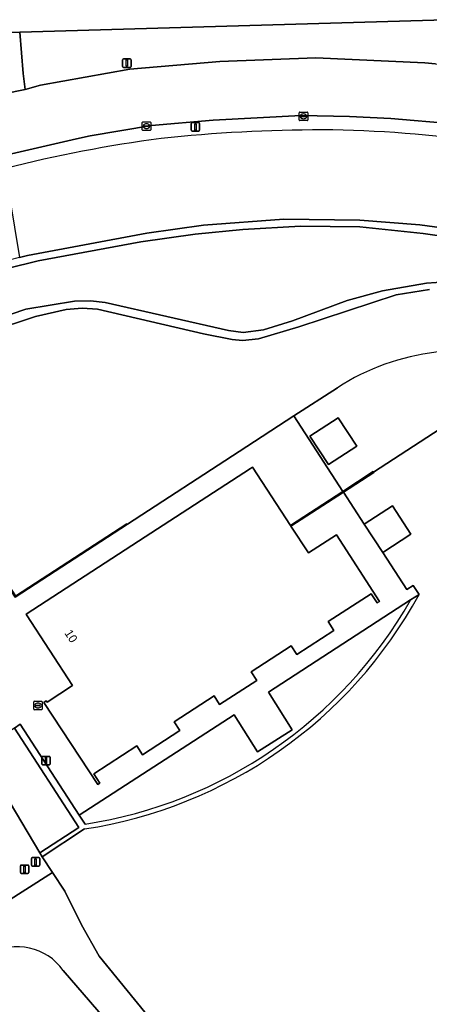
# Model space of a CAD drawing. Extents: x 159451 to 160664, y 388402 to 389723.
# Drawn here: x 160045.5 to 160093.7, y 389263 to 389378.7 of the extents above; entities that cross this region are included whole.
import ezdxf

# ---------------------------------------------------------------- set-up
doc = ezdxf.new("R2010")
doc.units = 0
for name, color, linetype in [('IMGEO_Afsluitpaal', 7, 'Continuous'), ('IMGEO_Erf', 7, 'Continuous'), ('IMGEO_Grasland_overig', 7, 'Continuous'), ('IMGEO_Groenvoorziening', 7, 'Continuous'), ('IMGEO_Haag', 7, 'Continuous'), ('IMGEO_Kolk', 7, 'Continuous'), ('IMGEO_Lichtmast', 7, 'Continuous'), ('IMGEO_Loofbos', 7, 'Continuous'), ('IMGEO_Meer_plas_ven_vijver', 7, 'Continuous'), ('IMGEO_Muur', 7, 'Continuous'), ('IMGEO_Oever', 7, 'Continuous'), ('IMGEO_Open_loods', 7, 'Continuous'), ('IMGEO_Pand', 7, 'Continuous'), ('IMGEO_Pand_nummerreeks', 7, 'Continuous'), ('IMGEO_Parkeervlak_open', 7, 'Continuous'), ('IMGEO_Rijbaan_lokaal_gesloten', 7, 'Continuous'), ('IMGEO_Rijbaan_lokaal_open', 7, 'Continuous'), ('IMGEO_Rioolput', 7, 'Continuous'), ('IMGEO_Verkeersbordpaal', 7, 'Continuous'), ('IMGEO_Voetpad_open', 7, 'Continuous')]:
    doc.layers.add(name, color=color, linetype=linetype)

msp = doc.modelspace()

# ---------------------------------------------------------------- linework, layer by layer
at = {"layer": 'IMGEO_Afsluitpaal'}
for p, q in [((160047.01, 389280.19), (160047.8, 389280.19)), ((160047.8, 389280.19), (160047.01, 389280.19)), ((160045.62, 389278.43), (160045.62, 389279.22)), ((160045.62, 389279.22), (160045.62, 389278.43)), ((160045.72, 389279.32), (160046.51, 389279.32)), ((160046.51, 389279.32), (160045.72, 389279.32)), ((160046.61, 389279.22), (160046.61, 389278.43)), ((160046.61, 389278.43), (160046.61, 389279.22)), ((160046.91, 389279.29), (160046.91, 389280.09)), ((160046.91, 389280.09), (160046.91, 389279.29)), ((160047.8, 389279.19), (160047.01, 389279.19)), ((160047.01, 389279.19), (160047.8, 389279.19)), ((160047.9, 389280.09), (160047.9, 389279.29)), ((160047.9, 389279.29), (160047.9, 389280.09)), ((160046.51, 389278.33), (160045.72, 389278.33)), ((160045.72, 389278.33), (160046.51, 389278.33))]:
    msp.add_line(p, q, dxfattribs=at)
for points in [[(160046.04, 389279.2), (160046.19, 389279.2), (160046.19, 389278.45), (160046.04, 389278.45), (160046.04, 389279.2)], [(160047.33, 389280.06), (160047.48, 389280.06), (160047.48, 389279.31), (160047.33, 389279.31), (160047.33, 389280.06)]]:
    msp.add_lwpolyline(points, dxfattribs=at)
for centre, start, end in [((160047.01, 389280.09), 90, 180), ((160047.01, 389280.09), 90, 180), ((160047.8, 389280.09), 0, 90), ((160047.8, 389280.09), 360, 90), ((160045.72, 389279.22), 90, 180), ((160045.72, 389279.22), 90, 180), ((160046.51, 389279.22), 0, 90), ((160046.51, 389279.22), 360, 90), ((160047.01, 389279.29), 180, 270), ((160047.01, 389279.29), 180, 270), ((160047.8, 389279.29), 270, 0), ((160047.8, 389279.29), 270, 0), ((160045.72, 389278.43), 180, 270), ((160045.72, 389278.43), 180, 270), ((160046.51, 389278.43), 270, 0), ((160046.51, 389278.43), 270, 0)]:
    msp.add_arc(centre, 0.1, start, end, dxfattribs=at)
at = {"layer": 'IMGEO_Erf'}
msp.add_lwpolyline([(160062.76, 389252.92), (160050.65, 389266.93)], dxfattribs=at)
msp.add_arc((160045.28, 389263.1), 6.6, 35.5165, 119.9336, dxfattribs=at)
at = {"layer": 'IMGEO_Grasland_overig'}
msp.add_lwpolyline([(160082.86, 389335.4), (160077.76, 389332.09), (160083.51, 389323.23), (160087.08, 389325.55), (160087.11, 389325.5), (160106.68, 389338.21)], dxfattribs=at)
msp.add_lwpolyline([(160081.8, 389326.37), (160079.62, 389329.72), (160082.96, 389331.88), (160085.13, 389328.54)], close=True, dxfattribs=at)
msp.add_arc((160097.62, 389312.67), 27.1, 70.4641, 123.0081, dxfattribs=at)
at = {"layer": 'IMGEO_Groenvoorziening'}
for points in [[(160039.74, 389411.81), (160043.52, 389377.12), (160045.57, 389377.18), (160095.57, 389378.65), (160130.29, 389372.3), (160147.5, 389362.17), (160157.28, 389356.45), (160160.93, 389357.29), (160193.04, 389391.96)], [(160043.81, 389361.18), (160045.51, 389350.7), (160046.47, 389350.95), (160060.48, 389353.57), (160067.14, 389354.51), (160076.55, 389355.23), (160085.49, 389355.12), (160092.55, 389354.57), (160100.3, 389353.49), (160106.52, 389352.35), (160119.77, 389349.05), (160128.5, 389346), (160138.33, 389341.84), (160146.63, 389337.26), (160151.81, 389333.78), (160161.69, 389326.54), (160174.13, 389316.33), (160188.05, 389305.74), (160195.54, 389299.58), (160200, 389295.53), (160201.33, 389293.98), (160202.93, 389291.68)], [(160091.46, 389310.47), (160074.77, 389299.62), (160077.56, 389295.2), (160073.49, 389292.64), (160070.73, 389296.99), (160052.54, 389285.17), (160053.22, 389284.13)], [(160092.45, 389311.11), (160091.46, 389310.47)], [(160053.22, 389284.13), (160052.54, 389285.17), (160045.6, 389295.86), (160044.94, 389295.4), (160052.48, 389283.74), (160047.89, 389280.74), (160048.18, 389280.3), (160053.14, 389283.56)]]:
    msp.add_lwpolyline(points, dxfattribs=at)
msp.add_lwpolyline([(160147.5, 389362.17), (160130.29, 389372.3), (160095.57, 389378.65), (160045.57, 389377.18), (160045.93, 389372.32), (160046.19, 389370.47), (160048, 389370.98), (160058.46, 389372.84), (160069.05, 389373.76), (160080.31, 389374.18), (160093.14, 389373.59), (160094.37, 389373.48), (160107.09, 389371.78), (160119.61, 389368.96), (160127.38, 389366.51), (160143.85, 389360.12), (160149.73, 389357.29), (160158.02, 389352.63), (160160.93, 389357.29), (160157.28, 389356.45)], close=True, dxfattribs=at)
for centre, radius, start, end in [((160083.13, 389205.47), 160.6, 97.5056, 104.1693), ((160080.95, 389193.32), 172.39, 89.9479, 96.2604), ((160080.26, 389233.45), 132.27, 81.218, 89.6361), ((160045.07, 389336.91), 53.95, 278.6038, 331.4356), ((160045.07, 389336.9), 53.4, 278.7798, 330.3246), ((160045.07, 389336.9), 53.4, 278.7798, 330.3246)]:
    msp.add_arc(centre, radius, start, end, dxfattribs=at)
at = {"layer": 'IMGEO_Haag'}
for points in [[(160092.45, 389311.11), (160091.46, 389310.47)], [(160053.22, 389284.13), (160052.54, 389285.17), (160045.6, 389295.86), (160044.94, 389295.4), (160052.48, 389283.74), (160047.89, 389280.74), (160048.18, 389280.3), (160053.14, 389283.56)]]:
    msp.add_lwpolyline(points, dxfattribs=at)
for centre, radius, start, end in [((160045.07, 389336.91), 53.95, 278.6038, 331.4356), ((160045.07, 389336.9), 53.4, 278.7798, 330.3246)]:
    msp.add_arc(centre, radius, start, end, dxfattribs=at)
at = {"layer": 'IMGEO_Kolk'}
for p, q in [((160078.38, 389366.87), (160078.38, 389367.73)), ((160078.45, 389367.8), (160079.31, 389367.8)), ((160078.64, 389367.29), (160078.64, 389367.31)), ((160078.68, 389367.34), (160079.08, 389367.34)), ((160079.08, 389367.26), (160078.68, 389367.26)), ((160078.87, 389367.58), (160078.89, 389367.58)), ((160078.89, 389367.02), (160078.87, 389367.02)), ((160079.12, 389367.31), (160079.12, 389367.29)), ((160079.38, 389367.73), (160079.38, 389366.87)), ((160059.94, 389365.73), (160059.94, 389366.58)), ((160060.01, 389366.65), (160060.86, 389366.65)), ((160060.19, 389366.15), (160060.19, 389366.16)), ((160060.63, 389366.11), (160060.23, 389366.11)), ((160060.24, 389366.2), (160060.63, 389366.2)), ((160060.42, 389366.43), (160060.45, 389366.43)), ((160060.45, 389365.87), (160060.42, 389365.87)), ((160060.68, 389366.16), (160060.68, 389366.15)), ((160060.94, 389366.58), (160060.94, 389365.73)), ((160079.31, 389366.8), (160078.45, 389366.8)), ((160060.86, 389365.65), (160060.01, 389365.65))]:
    msp.add_line(p, q, dxfattribs=at)
for points in [[(160078.38, 389366.87), (160078.38, 389367.73)], [(160078.45, 389367.8), (160079.31, 389367.8)], [(160079.38, 389367.73), (160079.38, 389366.87)], [(160059.94, 389365.73), (160059.94, 389366.58)], [(160060.01, 389366.65), (160060.86, 389366.65)], [(160060.94, 389366.58), (160060.94, 389365.73)], [(160079.31, 389366.8), (160078.45, 389366.8)], [(160060.86, 389365.65), (160060.01, 389365.65)]]:
    msp.add_lwpolyline(points, dxfattribs=at)
for centre, radius, start, end in [((160078.46, 389367.73), 0.0765, 91.552, 178.448), ((160078.46, 389367.73), 0.0765, 91.552, 178.448), ((160078.68, 389367.3), 0.0403, 85.8775, 175.7526), ((160078.68, 389367.29), 0.0366, 178.938, 274.7102), ((160079.08, 389367.31), 0.0386, 1.7309, 96.639), ((160079.08, 389367.3), 0.043, 264.8664, 352.4533), ((160079.3, 389367.73), 0.0765, 1.552, 88.448), ((160079.3, 389367.73), 0.0765, 1.552, 88.448), ((160060.01, 389366.58), 0.0765, 91.552, 178.448), ((160060.01, 389366.58), 0.0765, 91.552, 178.448), ((160060.23, 389366.16), 0.0403, 85.8775, 175.7526), ((160060.23, 389366.15), 0.0366, 178.938, 274.7102), ((160060.64, 389366.16), 0.0386, 1.7309, 96.639), ((160060.64, 389366.15), 0.043, 264.8664, 352.4533), ((160060.86, 389366.58), 0.0765, 1.552, 88.448), ((160060.86, 389366.58), 0.0765, 1.552, 88.448), ((160078.46, 389366.88), 0.0765, 181.552, 268.448), ((160078.46, 389366.88), 0.0765, 181.552, 268.448), ((160079.3, 389366.88), 0.0765, 271.552, 358.448), ((160079.3, 389366.88), 0.0765, 271.552, 358.448), ((160060.01, 389365.73), 0.0765, 181.552, 268.448), ((160060.01, 389365.73), 0.0765, 181.552, 268.448), ((160060.86, 389365.73), 0.0765, 271.552, 358.448), ((160060.86, 389365.73), 0.0765, 271.552, 358.448)]:
    msp.add_arc(centre, radius, start, end, dxfattribs=at)
for centre, major_axis, ratio, start_param, end_param in [((160078.87, 389367.3), (-0.387, 0.002), 0.722429, 4.712389, 7.853982), ((160078.89, 389367.3), (-0.39, 0.002), 0.717154, 1.570796, 4.712389), ((160060.42, 389366.15), (-0.387, 0.002), 0.722429, 4.712389, 7.853982), ((160060.45, 389366.15), (-0.39, 0.002), 0.717154, 1.570796, 4.712389)]:
    msp.add_ellipse(centre, major_axis=major_axis, ratio=ratio, start_param=start_param, end_param=end_param, dxfattribs=at)
at = {"layer": 'IMGEO_Lichtmast'}
for p, q in [((160065.7, 389365.67), (160065.7, 389366.47)), ((160065.7, 389366.47), (160065.7, 389365.67)), ((160065.8, 389366.57), (160066.58, 389366.57)), ((160066.58, 389366.57), (160065.8, 389366.57)), ((160066.68, 389366.47), (160066.68, 389365.67)), ((160066.68, 389365.67), (160066.68, 389366.47)), ((160066.58, 389365.57), (160065.8, 389365.57)), ((160065.8, 389365.57), (160066.58, 389365.57)), ((160048.13, 389291.19), (160048.13, 389291.99)), ((160048.13, 389291.99), (160048.13, 389291.19)), ((160048.23, 389292.09), (160049.02, 389292.09)), ((160049.02, 389292.09), (160048.23, 389292.09)), ((160049.12, 389291.99), (160049.12, 389291.19)), ((160049.12, 389291.19), (160049.12, 389291.99)), ((160049.02, 389291.09), (160048.23, 389291.09)), ((160048.23, 389291.09), (160049.02, 389291.09))]:
    msp.add_line(p, q, dxfattribs=at)
for points in [[(160066.11, 389366.44), (160066.27, 389366.44), (160066.27, 389365.69), (160066.11, 389365.69), (160066.11, 389366.44)], [(160048.55, 389291.96), (160048.7, 389291.96), (160048.7, 389291.21), (160048.55, 389291.21), (160048.55, 389291.96)]]:
    msp.add_lwpolyline(points, dxfattribs=at)
for centre, start, end in [((160065.8, 389366.47), 90, 180), ((160065.8, 389366.47), 90, 180), ((160066.58, 389366.47), 0, 90), ((160066.58, 389366.47), 360, 90), ((160065.8, 389365.67), 180, 270), ((160065.8, 389365.67), 180, 270), ((160066.58, 389365.67), 270, 0), ((160066.58, 389365.67), 270, 0), ((160048.23, 389291.99), 90, 180), ((160048.23, 389291.99), 90, 180), ((160049.02, 389291.99), 0, 90), ((160049.02, 389291.99), 360, 90), ((160048.23, 389291.19), 180, 270), ((160048.23, 389291.19), 180, 270), ((160049.02, 389291.19), 270, 0), ((160049.02, 389291.19), 270, 0)]:
    msp.add_arc(centre, 0.1, start, end, dxfattribs=at)
at = {"layer": 'IMGEO_Loofbos'}
for points in [[(160093.68, 389346.96), (160089.75, 389346.34), (160078.34, 389342.57), (160073.6, 389341.14), (160071.7, 389340.98), (160070.48, 389341.07), (160067.13, 389341.76), (160054.69, 389344.63), (160052.87, 389344.77), (160051.01, 389344.59), (160047.4, 389343.78), (160042.04, 389342.02), (160039.76, 389341.39), (160037.8, 389340.37), (160032.74, 389337.96), (160031.5, 389337.66), (160029.54, 389336.58)], [(160106.68, 389338.21), (160087.11, 389325.5), (160087.14, 389325.45), (160083.58, 389323.13), (160086.02, 389319.37), (160089.33, 389321.52), (160091.49, 389318.19), (160088.19, 389316.04), (160091, 389311.7), (160091.77, 389312.18), (160092.45, 389311.11)], [(160030.04, 389332.25), (160030.79, 389332.74), (160045.01, 389310.81), (160058.19, 389319.37), (160071.34, 389327.91), (160077.76, 389332.09), (160082.86, 389335.4)], [(160053.14, 389283.56), (160048.18, 389280.3), (160049.4, 389278.45), (160050.84, 389276.24), (160052.78, 389272.29), (160054.86, 389268.6), (160063.52, 389257.98), (160075, 389246.59)]]:
    msp.add_lwpolyline(points, dxfattribs=at)
for centre, radius, start, end in [((160097.62, 389312.67), 27.1, 70.4641, 123.0081), ((160045.07, 389336.91), 53.95, 278.6038, 331.4356)]:
    msp.add_arc(centre, radius, start, end, dxfattribs=at)
at = {"layer": 'IMGEO_Meer_plas_ven_vijver'}
for points in [[(160100.93, 389352.39), (160092.92, 389353.53), (160085.48, 389354.3), (160078.54, 389354.41), (160071.77, 389354), (160066.16, 389353.46), (160059.75, 389352.54), (160047.7, 389350.34), (160044.05, 389349.44)], [(160033.8, 389340.41), (160046.26, 389344.65), (160051.98, 389345.6), (160053.84, 389345.62), (160055.56, 389345.42), (160070.07, 389342.15), (160071.81, 389341.89), (160074.18, 389342.21), (160077.59, 389343.28), (160084.02, 389345.67), (160088.15, 389346.81), (160093.34, 389347.7), (160095.6, 389347.84)]]:
    msp.add_lwpolyline(points, dxfattribs=at)
at = {"layer": 'IMGEO_Muur'}
for points in [[(160045.57, 389377.18), (160095.57, 389378.65), (160130.29, 389372.3), (160147.5, 389362.17)], [(160030.79, 389332.74), (160030.58, 389333.06), (160030.68, 389333.12), (160045.04, 389310.96), (160058.13, 389319.46)], [(160058.19, 389319.37), (160045.01, 389310.81), (160030.79, 389332.74)]]:
    msp.add_lwpolyline(points, dxfattribs=at)
msp.add_lwpolyline([(160087.11, 389325.5), (160087.08, 389325.55), (160083.51, 389323.23), (160077.35, 389319.23), (160077.41, 389319.13), (160083.58, 389323.13), (160087.14, 389325.45)], close=True, dxfattribs=at)
at = {"layer": 'IMGEO_Oever'}
for points in [[(160100.3, 389353.49), (160092.55, 389354.57), (160085.49, 389355.12), (160076.55, 389355.23), (160067.14, 389354.51), (160060.48, 389353.57), (160046.47, 389350.95), (160045.51, 389350.7), (160040.63, 389349.45), (160033.58, 389347.08), (160026.21, 389344.02), (160022.19, 389342.23), (160018.4, 389340.07)], [(160047.7, 389350.34), (160059.75, 389352.54), (160066.16, 389353.46), (160071.77, 389354), (160078.54, 389354.41), (160085.48, 389354.3), (160092.92, 389353.53), (160100.93, 389352.39)], [(160095.6, 389347.84), (160093.34, 389347.7), (160088.15, 389346.81), (160084.02, 389345.67), (160077.59, 389343.28), (160074.18, 389342.21), (160071.81, 389341.89), (160070.07, 389342.15), (160055.56, 389345.42), (160053.84, 389345.62), (160051.98, 389345.6), (160046.26, 389344.65), (160033.8, 389340.41), (160029.12, 389338.46), (160024.82, 389336.57), (160020.98, 389334.55), (160019.88, 389336.53), (160018.52, 389338.99), (160022.63, 389341.28), (160028.21, 389343.7), (160036.6, 389347.15), (160044.05, 389349.44), (160047.7, 389350.34)], [(160021.85, 389333.02), (160029.54, 389336.58), (160031.5, 389337.66), (160032.74, 389337.96), (160037.8, 389340.37), (160039.76, 389341.39), (160042.04, 389342.02), (160047.4, 389343.78), (160051.01, 389344.59), (160052.87, 389344.77), (160054.69, 389344.63), (160067.13, 389341.76), (160070.48, 389341.07), (160071.7, 389340.98), (160073.6, 389341.14), (160078.34, 389342.57), (160089.75, 389346.34), (160093.68, 389346.96)]]:
    msp.add_lwpolyline(points, dxfattribs=at)
at = {"layer": 'IMGEO_Open_loods'}
for points in [[(160082.96, 389331.88), (160079.62, 389329.72), (160081.8, 389326.37), (160085.13, 389328.54)], [(160089.33, 389321.52), (160086.02, 389319.37), (160088.19, 389316.04), (160091.49, 389318.19)]]:
    msp.add_lwpolyline(points, close=True, dxfattribs=at)
at = {"layer": 'IMGEO_Pand'}
msp.add_lwpolyline([(160077.41, 389319.13), (160077.35, 389319.23), (160072.9, 389326.07), (160072.64, 389325.9), (160059.5, 389317.36), (160046.31, 389308.79), (160046.33, 389308.74), (160051.75, 389300.4), (160048.76, 389298.46), (160048.65, 389298.63), (160048.36, 389298.44), (160054.7, 389288.78), (160054.96, 389288.95), (160054.25, 389290.03), (160059.31, 389293.32), (160059.98, 389292.29), (160064.34, 389295.13), (160063.67, 389296.15), (160068.37, 389299.2), (160069.03, 389298.18), (160073.39, 389301.01), (160072.73, 389302.04), (160077.42, 389305.09), (160078.09, 389304.06), (160082.45, 389306.9), (160081.79, 389307.92), (160086.84, 389311.2), (160087.54, 389310.12), (160087.82, 389310.3), (160082.74, 389318.12), (160079.45, 389315.99)], close=True, dxfattribs=at)
at = {"layer": 'IMGEO_Parkeervlak_open'}
msp.add_lwpolyline([(160047.89, 389280.74), (160052.48, 389283.74), (160044.94, 389295.4), (160040.78, 389292.71)], close=True, dxfattribs=at)
at = {"layer": 'IMGEO_Rijbaan_lokaal_gesloten'}
for points in [[(160094.37, 389373.48), (160093.14, 389373.59), (160080.31, 389374.18), (160069.05, 389373.76), (160058.46, 389372.84), (160048, 389370.98), (160046.19, 389370.47), (160036.11, 389368.42), (160024.31, 389363.83), (160022.75, 389363.16), (160022.23, 389362.94), (160011.54, 389358.23), (160005.85, 389355.23), (160000, 389351.61), (159986.35, 389343.16), (159930.8, 389307.35), (159895.87, 389284.58)], [(159899.83, 389278.61), (159906.38, 389282.87), (159947.89, 389309.89), (159973.82, 389326.76), (159998.77, 389342.96), (160007.26, 389348.15), (160010.77, 389350.12), (160016.23, 389352.7), (160018.64, 389353.83), (160032.2, 389359.34), (160040.87, 389362.06), (160043.57, 389362.68), (160052.23, 389364.66), (160053.83, 389365.02), (160061.03, 389366.23), (160068.28, 389366.86), (160078.59, 389367.39), (160084.27, 389367.3), (160089.12, 389367.06), (160096.48, 389366.43)], [(160050.65, 389266.93), (160062.76, 389252.92), (160072.99, 389243.15), (160076.29, 389245.32), (160075, 389246.59), (160063.52, 389257.98), (160054.86, 389268.6), (160052.78, 389272.29), (160050.84, 389276.24), (160049.4, 389278.45), (160043.54, 389274.71), (159994.77, 389243.39), (159993.51, 389242.58), (159975.92, 389231.28)]]:
    msp.add_lwpolyline(points, dxfattribs=at)
msp.add_arc((160045.28, 389263.1), 6.6, 35.5165, 119.9336, dxfattribs=at)
at = {"layer": 'IMGEO_Rijbaan_lokaal_open'}
msp.add_lwpolyline([(160043.47, 389274.82), (160043.54, 389274.71), (160049.4, 389278.45), (160048.18, 389280.3), (160047.89, 389280.74), (160040.78, 389292.71), (160039.64, 389294.47), (160023.01, 389320.16)], dxfattribs=at)
at = {"layer": 'IMGEO_Rioolput'}
for p, q in [((160047.18, 389297.65), (160047.18, 389298.5)), ((160047.25, 389298.57), (160048.11, 389298.57)), ((160048.11, 389297.57), (160047.25, 389297.57)), ((160047.44, 389298.07), (160047.44, 389298.08)), ((160047.48, 389298.12), (160047.88, 389298.12)), ((160047.88, 389298.03), (160047.48, 389298.03)), ((160047.69, 389297.79), (160047.66, 389297.79)), ((160047.67, 389298.35), (160047.69, 389298.35)), ((160047.92, 389298.08), (160047.92, 389298.07)), ((160048.18, 389298.5), (160048.18, 389297.65))]:
    msp.add_line(p, q, dxfattribs=at)
for points in [[(160047.18, 389297.65), (160047.18, 389298.5)], [(160047.25, 389298.57), (160048.11, 389298.57)], [(160048.11, 389297.57), (160047.25, 389297.57)], [(160048.18, 389298.5), (160048.18, 389297.65)]]:
    msp.add_lwpolyline(points, dxfattribs=at)
for centre, radius, start, end in [((160047.26, 389298.5), 0.0765, 91.552, 178.448), ((160047.26, 389298.5), 0.0765, 91.552, 178.448), ((160047.26, 389297.65), 0.0765, 181.552, 268.448), ((160047.26, 389297.65), 0.0765, 181.552, 268.448), ((160047.48, 389298.08), 0.0403, 85.8775, 175.7526), ((160047.47, 389298.07), 0.0366, 178.938, 274.7102), ((160047.88, 389298.08), 0.0386, 1.7309, 96.639), ((160047.88, 389298.07), 0.043, 264.8664, 352.4533), ((160048.1, 389298.5), 0.0765, 1.552, 88.448), ((160048.1, 389298.5), 0.0765, 1.552, 88.448), ((160048.1, 389297.65), 0.0765, 271.552, 358.448), ((160048.1, 389297.65), 0.0765, 271.552, 358.448)]:
    msp.add_arc(centre, radius, start, end, dxfattribs=at)
for centre, major_axis, ratio, start_param, end_param in [((160047.67, 389298.07), (-0.387, 0.002), 0.722429, 4.712389, 7.853982), ((160047.69, 389298.07), (-0.39, 0.002), 0.717154, 1.570796, 4.712389)]:
    msp.add_ellipse(centre, major_axis=major_axis, ratio=ratio, start_param=start_param, end_param=end_param, dxfattribs=at)
at = {"layer": 'IMGEO_Verkeersbordpaal'}
for p, q in [((160057.63, 389373.16), (160057.63, 389373.96)), ((160057.63, 389373.96), (160057.63, 389373.16)), ((160057.73, 389374.06), (160058.52, 389374.06)), ((160058.52, 389374.06), (160057.73, 389374.06)), ((160058.62, 389373.96), (160058.62, 389373.16)), ((160058.62, 389373.16), (160058.62, 389373.96)), ((160058.52, 389373.06), (160057.73, 389373.06)), ((160057.73, 389373.06), (160058.52, 389373.06))]:
    msp.add_line(p, q, dxfattribs=at)
msp.add_lwpolyline([(160058.05, 389373.93), (160058.2, 389373.93), (160058.2, 389373.18), (160058.05, 389373.18), (160058.05, 389373.93)], dxfattribs=at)
for centre, start, end in [((160057.73, 389373.96), 90, 180), ((160057.73, 389373.96), 90, 180), ((160058.52, 389373.96), 0, 90), ((160058.52, 389373.96), 360, 90), ((160057.73, 389373.16), 180, 270), ((160057.73, 389373.16), 180, 270), ((160058.52, 389373.16), 270, 0), ((160058.52, 389373.16), 270, 0)]:
    msp.add_arc(centre, 0.1, start, end, dxfattribs=at)
at = {"layer": 'IMGEO_Voetpad_open'}
msp.add_lwpolyline([(160039.74, 389411.81), (160032.85, 389484.66), (160029, 389484.38), (160030.41, 389470.42), (160038.58, 389384.31), (160039.49, 389376.11), (160039.62, 389374.92), (160037.55, 389374.64), (160038.03, 389371.1), (160036.04, 389370.93), (160036.17, 389368.93), (160036.11, 389368.42), (160046.19, 389370.47), (160045.93, 389372.32), (160045.57, 389377.18), (160043.52, 389377.12)], close=True, dxfattribs=at)
for points in [[(160096.48, 389366.43), (160089.12, 389367.06), (160084.27, 389367.3), (160078.59, 389367.39), (160068.28, 389366.86), (160061.03, 389366.23), (160053.83, 389365.02), (160052.23, 389364.66), (160043.57, 389362.68), (160040.87, 389362.06), (160032.2, 389359.34), (160018.64, 389353.83), (160016.23, 389352.7), (160010.77, 389350.12), (160007.26, 389348.15), (160009.65, 389343.89), (160010.35, 389344.37), (160008.64, 389346.99)], [(160044.94, 389295.4), (160045.6, 389295.86), (160052.54, 389285.17), (160070.73, 389296.99), (160073.49, 389292.64), (160077.56, 389295.2), (160074.77, 389299.62), (160091.46, 389310.47), (160092.45, 389311.11), (160091.77, 389312.18), (160091, 389311.7), (160088.19, 389316.04), (160086.02, 389319.37), (160083.58, 389323.13), (160077.41, 389319.13), (160079.45, 389315.99), (160082.74, 389318.12), (160087.82, 389310.3), (160087.54, 389310.12), (160086.84, 389311.2), (160081.79, 389307.92), (160082.45, 389306.9), (160078.09, 389304.06), (160077.42, 389305.09), (160072.73, 389302.04), (160073.39, 389301.01), (160069.03, 389298.18), (160068.37, 389299.2), (160063.67, 389296.15), (160064.34, 389295.13), (160059.98, 389292.29), (160059.31, 389293.32), (160054.25, 389290.03), (160054.96, 389288.95), (160054.7, 389288.78), (160048.36, 389298.44), (160048.65, 389298.63), (160048.76, 389298.46), (160051.75, 389300.4), (160046.33, 389308.74), (160046.31, 389308.79), (160059.5, 389317.36), (160072.64, 389325.9), (160072.9, 389326.07), (160077.35, 389319.23), (160083.51, 389323.23), (160077.76, 389332.09), (160071.34, 389327.91), (160058.19, 389319.37), (160045.01, 389310.81)]]:
    msp.add_lwpolyline(points, dxfattribs=at)
for centre, radius, start, end in [((160083.13, 389205.47), 160.6, 97.5056, 104.1693), ((160080.95, 389193.32), 172.39, 89.9479, 96.2604), ((160080.26, 389233.45), 132.27, 81.218, 89.6361)]:
    msp.add_arc(centre, radius, start, end, dxfattribs=at)

# ---------------------------------------------------------------- texts
at = {"layer": 'IMGEO_Pand_nummerreeks'}
msp.add_text('10', height=1, rotation=303.0096, dxfattribs=at).set_placement((160050.75, 389306.58))

doc.saveas('drawing.dxf')
